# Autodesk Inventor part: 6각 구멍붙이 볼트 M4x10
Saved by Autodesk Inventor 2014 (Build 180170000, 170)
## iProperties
Created: 2026-05
Part Number: 6각 구멍붙이 볼트 M4x10
Material: 일반
Document SubType Name: Modeling
Designer: dg
Density: 1 g/cm^3
Appearance: 기본값
Author: dg
Author: jhkim
Description: 6각머리 태핑 나사
Creation Date: 2026-04-27
Sending System: Autodesk Inventor 2027
Preprocessor: ST-DEVELOPER v20.1
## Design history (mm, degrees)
node "6각 구멍붙이 볼트 M4x101"
body "Solid1"
node "기준1"
